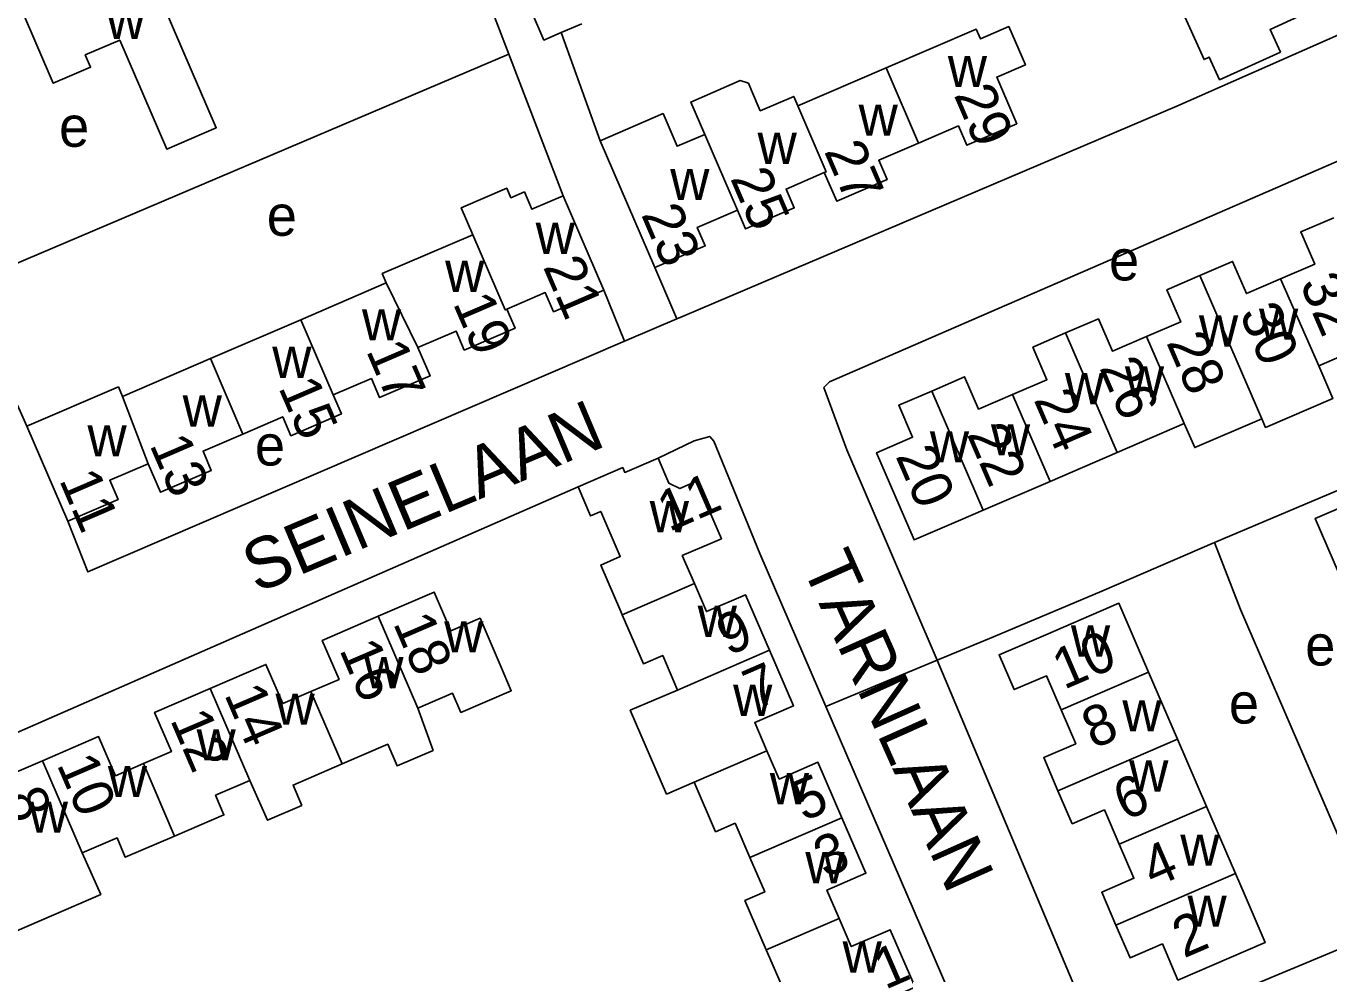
# Model space of a CAD drawing. Extents: x 157768 to 159790, y 387230 to 389604.
# Drawn here: x 158163.8 to 158292.2, y 388618.6 to 388712 of the extents above; entities that cross this region are included whole.
import ezdxf

# ---------------------------------------------------------------- set-up
doc = ezdxf.new("R2010")
doc.units = 0
for name, color, linetype in [('BLT_Basislijn', 7, 'Continuous'), ('BLT_Bebouwing', 7, 'Continuous'), ('BLT_Centroide', 7, 'Continuous'), ('BLT_Huisnummer', 7, 'Continuous'), ('BLT_Huisnummer_ tussenligend', 7, 'Continuous'), ('BLT_Onderverdeling_panden', 7, 'Continuous'), ('BLT_Straatnaam', 7, 'Continuous'), ('BLT_Vlakafsluiter', 7, 'Continuous')]:
    doc.layers.add(name, color=color, linetype=linetype)

msp = doc.modelspace()

# ---------------------------------------------------------------- linework, layer by layer
at = {"layer": 'BLT_Basislijn'}
for p, q in [((158211.37, 388709.21), (158205.74, 388723.88)), ((158220.36, 388700.68), (158216.53, 388711.33)), ((158157.67, 388686.38), (158211.37, 388709.21)), ((158216.72, 388695.26), (158211.37, 388709.21)), ((158227.91, 388683.12), (158225.75, 388688.17)), ((158163.87, 388672.54), (158157.67, 388686.38)), ((158222.77, 388680.91), (158220.72, 388685.96))]:
    msp.add_line(p, q, dxfattribs=at)
for points in [[(158228.87, 388771.67), (158290.41, 388727.23), (158290.89, 388726.75), (158296.54, 388713.1), (158296.49, 388712.58), (158277.19, 388704.08), (158228.72, 388683.47), (158227.91, 388683.12)], [(158253.57, 388649.48), (158244.69, 388670.2), (158242.42, 388676.37), (158242.96, 388676.91), (158323.61, 388711.93)], [(158222.77, 388680.91), (158223.24, 388681.11), (158227.91, 388683.12)], [(158167.9, 388663.18), (158169.88, 388658.18), (158222.77, 388680.91)], [(158226.07, 388669.41), (158229.62, 388671.09), (158231.17, 388671.54), (158231.58, 388671.07), (158236.09, 388660.01), (158242.61, 388644.93)], [(158303.84, 388670.77), (158292.19, 388665.85), (158280.9, 388661.07)], [(158121.28, 388623.33), (158122.08, 388624.5), (158218.19, 388666.56)], [(158280.9, 388661.07), (158269.8, 388656.28), (158259.12, 388651.77), (158253.57, 388649.48)], [(158280.9, 388661.07), (158283.46, 388654.49), (158297.22, 388622.68)], [(158253.57, 388649.48), (158269.51, 388611.63), (158271, 388611.74), (158297.22, 388622.68)], [(158242.61, 388644.93), (158255.37, 388615.4), (158255.28, 388614.44), (158187.04, 388585.65), (158156.23, 388567.27)]]:
    msp.add_lwpolyline(points, dxfattribs=at)
at = {"layer": 'BLT_Bebouwing'}
for p, q in [((158218.55, 388712.2), (158216.53, 388711.33)), ((158239.84, 388704.11), (158248.55, 388707.86)), ((158225.75, 388688.17), (158220.36, 388700.68)), ((158216.72, 388695.26), (158220.72, 388685.96)), ((158190.86, 388683.04), (158199.28, 388686.67)), ((158181.95, 388679.21), (158190.86, 388683.04)), ((158173.29, 388675.48), (158181.95, 388679.21)), ((158167.9, 388663.18), (158163.87, 388672.54)), ((158271.32, 388669.95), (158277.92, 388672.8)), ((158264.71, 388667.1), (158271.32, 388669.95)), ((158258.1, 388664.26), (158264.71, 388667.1)), ((158277.26, 388641.7), (158274.41, 388648.31)), ((158280.12, 388635.07), (158277.26, 388641.7)), ((158282.97, 388628.46), (158280.12, 388635.07))]:
    msp.add_line(p, q, dxfattribs=at)
for points in [[(158169.97, 388720.68), (158170.31, 388719.87), (158174.1, 388721.5), (158182.53, 388701.95), (158177.66, 388699.85), (158173.02, 388710.59), (158169.62, 388709.13), (158170.14, 388707.93), (158166.46, 388706.35), (158161.81, 388717.15), (158169.97, 388720.68)], [(158282.98, 388721.85), (158285.21, 388716.94), (158286.99, 388717.74), (158289.18, 388712.92), (158286.39, 388711.65), (158287.41, 388709.42), (158281.42, 388706.68), (158280.4, 388708.92), (158279.89, 388708.68), (158275.94, 388717.43)], [(158216.53, 388711.33), (158214.82, 388710.6), (158213.6, 388713.41), (158215.41, 388714.19)], [(158248.55, 388707.86), (158257.42, 388711.68), (158257.84, 388710.71), (158260.65, 388711.93), (158262.28, 388708.16), (158259.46, 388706.95), (158261.43, 388702.35), (158256.5, 388700.23), (158255.68, 388702.13), (158251.75, 388700.44)], [(158230.67, 388701.3), (158229.29, 388704.49), (158234.18, 388706.6), (158234.98, 388706.36), (158235.29, 388705.64), (158236.15, 388703.63), (158239.44, 388705.05), (158239.84, 388704.11)], [(158220.36, 388700.68), (158226.56, 388703.35), (158227.94, 388700.13), (158230.67, 388701.3)], [(158251.75, 388700.44), (158247.83, 388698.75), (158248.64, 388696.85), (158243.68, 388694.71), (158242.46, 388697.54)], [(158242.46, 388697.54), (158238.69, 388695.91), (158239.49, 388694.06), (158234.7, 388691.99), (158233.9, 388693.84)], [(158207.81, 388691.42), (158206.67, 388694.07), (158211.16, 388696.01), (158211.57, 388695.06), (158212.9, 388695.63), (158213.64, 388693.93), (158216.72, 388695.26)], [(158233.9, 388693.84), (158229.94, 388692.14), (158230.73, 388690.31), (158225.75, 388688.17)], [(158287.42, 388687.07), (158290.79, 388688.51), (158289.42, 388691.69), (158292.66, 388693.09)], [(158199.28, 388686.67), (158198.89, 388687.58), (158207.81, 388691.42)], [(158279.46, 388687.4), (158282.69, 388688.79), (158284.06, 388685.62), (158287.42, 388687.07)], [(158274.22, 388681.38), (158277.59, 388682.83), (158276.23, 388686), (158279.46, 388687.4)], [(158220.72, 388685.96), (158215.77, 388683.83), (158214.95, 388685.71), (158211.18, 388684.08)], [(158211.18, 388684.08), (158211.99, 388682.2), (158206.98, 388680.04), (158206.17, 388681.92), (158202.4, 388680.3)], [(158266.24, 388681.73), (158269.48, 388683.12), (158270.86, 388679.93), (158274.22, 388681.38)], [(158261.02, 388675.68), (158264.39, 388677.13), (158263.01, 388680.33), (158266.24, 388681.73)], [(158291.18, 388678.51), (158297.78, 388681.36)], [(158202.4, 388680.3), (158203.61, 388677.5), (158198.63, 388675.36), (158197.82, 388677.24), (158194.06, 388675.62)], [(158253.04, 388676.01), (158256.28, 388677.41), (158257.65, 388674.23), (158261.02, 388675.68)], [(158285.58, 388673.28), (158285.95, 388672.42), (158292.56, 388675.27), (158291.18, 388678.51)], [(158163.87, 388672.54), (158172.89, 388676.42), (158173.29, 388675.48)], [(158258.1, 388664.26), (158255.9, 388663.31), (158251.31, 388661.33), (158247.61, 388669.93), (158251.15, 388671.46), (158249.79, 388674.61), (158253.04, 388676.01)], [(158194.06, 388675.62), (158194.86, 388673.75), (158189.89, 388671.61), (158189.09, 388673.47), (158185.16, 388671.77)], [(158277.92, 388672.8), (158278.97, 388670.43), (158285.58, 388673.28)], [(158185.16, 388671.77), (158181.23, 388670.08), (158182.04, 388668.19), (158177.04, 388666.04), (158175.83, 388668.85)], [(158175.83, 388668.85), (158172.04, 388667.21), (158172.86, 388665.31), (158167.9, 388663.18)], [(158226.07, 388669.41), (158222.79, 388667.99), (158222.59, 388668.46), (158218.19, 388666.56)], [(158229.65, 388657.04), (158228.46, 388659.8), (158232.31, 388661.46), (158229.87, 388667.12), (158228.22, 388666.4), (158227.14, 388666.93), (158226.07, 388669.41)], [(158293.77, 388656.69), (158290.85, 388663.46), (158298.03, 388666.55), (158302.62, 388668.53), (158304.09, 388665.14), (158300.93, 388663.78), (158302.38, 388660.4)], [(158218.19, 388666.56), (158219.42, 388663.71), (158220.42, 388664.14), (158222.34, 388659.69), (158220.42, 388658.86), (158222.4, 388654.27), (158222.54, 388653.96)], [(158237.05, 388650.46), (158234.68, 388655.94), (158230.84, 388654.28), (158229.65, 388657.04)], [(158202.39, 388644.76), (158205.82, 388646.23), (158206.64, 388644.33), (158211.6, 388646.47), (158210.51, 388649.02), (158208.53, 388653.61), (158205.65, 388652.37), (158204.01, 388656.19), (158198.49, 388653.82)], [(158274.41, 388648.31), (158271.49, 388655.09), (158264.29, 388651.98), (158259.69, 388650), (158261.17, 388646.58), (158264.35, 388647.95), (158265.8, 388644.6)], [(158198.49, 388653.82), (158192.98, 388651.44), (158194.64, 388647.59), (158191.86, 388646.39)], [(158222.54, 388653.96), (158224.63, 388649.13), (158226.53, 388649.95), (158228, 388646.54)], [(158236.8, 388640.55), (158235.6, 388643.33), (158239.42, 388644.98), (158237.05, 388650.46)], [(158191.86, 388646.39), (158189.08, 388645.2), (158187.42, 388649.06), (158181.93, 388646.7)], [(158181.93, 388646.7), (158176.45, 388644.34), (158178.11, 388640.47), (158175.36, 388639.29)], [(158228, 388646.54), (158223.34, 388644.55), (158226.91, 388636.29), (158229.64, 388637.45)], [(158194.93, 388639.27), (158199.43, 388641.2), (158200.35, 388639.07), (158203.9, 388640.6), (158202.39, 388644.76)], [(158265.8, 388644.6), (158267.24, 388641.25), (158264.08, 388639.89), (158265.48, 388636.62)], [(158175.36, 388639.29), (158172.6, 388638.1), (158170.94, 388641.96), (158165.4, 388639.58)], [(158244.2, 388633.95), (158241.83, 388639.42), (158238.01, 388637.77), (158236.8, 388640.55)], [(158165.4, 388639.58), (158159.86, 388637.19), (158161.54, 388633.3), (158158.8, 388632.12)], [(158185.84, 388637.63), (158187.57, 388633.71), (158190.96, 388635.17), (158190.1, 388637.18), (158194.93, 388639.27)], [(158178.43, 388632.15), (158183.29, 388634.24), (158182.46, 388636.17), (158185.84, 388637.63)], [(158229.64, 388637.45), (158231.74, 388632.58), (158233.66, 388633.41), (158235.12, 388630.03)], [(158265.48, 388636.62), (158266.89, 388633.36), (158270.07, 388634.73), (158271.52, 388631.36)], [(158243.92, 388624.04), (158242.71, 388626.82), (158246.56, 388628.49), (158244.2, 388633.95)], [(158169.32, 388630.49), (158172.75, 388631.97), (158173.57, 388630.06), (158178.43, 388632.15)], [(158271.52, 388631.36), (158272.97, 388627.99), (158269.8, 388626.62), (158271.19, 388623.38)], [(158161.86, 388625.01), (158162.89, 388622.82), (158171.14, 388626.4), (158169.32, 388630.49)], [(158235.12, 388630.03), (158236.58, 388626.65), (158234.63, 388625.8), (158236.74, 388620.94)], [(158271.19, 388623.38), (158272.59, 388620.15), (158275.78, 388621.52), (158277.31, 388617.96), (158285.9, 388621.66), (158283.92, 388626.25), (158282.97, 388628.46)], [(158236.74, 388620.94), (158236.87, 388620.65), (158238.85, 388616.06), (158240.77, 388616.89), (158242.32, 388613.32), (158251.41, 388617.26), (158248.96, 388622.92), (158245.12, 388621.26), (158243.92, 388624.04)]]:
    msp.add_lwpolyline(points, dxfattribs=at)
at = {"layer": 'BLT_Onderverdeling_panden'}
for p, q in [((158251.75, 388700.44), (158248.55, 388707.86)), ((158233.9, 388693.84), (158230.67, 388701.3)), ((158202.4, 388680.3), (158199.28, 388686.67)), ((158279.46, 388687.4), (158285.58, 388673.28)), ((158287.42, 388687.07), (158291.18, 388678.51)), ((158194.06, 388675.62), (158190.86, 388683.04)), ((158266.24, 388681.73), (158271.32, 388669.95)), ((158274.22, 388681.38), (158277.92, 388672.8)), ((158185.16, 388671.77), (158181.95, 388679.21)), ((158253.04, 388676.01), (158258.1, 388664.26)), ((158173.29, 388675.48), (158175.83, 388668.85)), ((158261.02, 388675.68), (158264.71, 388667.1)), ((158229.65, 388657.04), (158222.54, 388653.96)), ((158198.49, 388653.82), (158202.39, 388644.76)), ((158237.05, 388650.46), (158228, 388646.54)), ((158265.8, 388644.6), (158274.41, 388648.31)), ((158181.93, 388646.7), (158185.84, 388637.63)), ((158191.86, 388646.39), (158194.93, 388639.27)), ((158265.48, 388636.62), (158277.26, 388641.7)), ((158236.8, 388640.55), (158229.64, 388637.45)), ((158165.4, 388639.58), (158169.32, 388630.49)), ((158175.36, 388639.29), (158178.43, 388632.15)), ((158271.52, 388631.36), (158280.12, 388635.07)), ((158244.2, 388633.95), (158235.12, 388630.03)), ((158271.19, 388623.38), (158282.97, 388628.46)), ((158243.92, 388624.04), (158236.74, 388620.94))]:
    msp.add_line(p, q, dxfattribs=at)
for points in [[(158239.84, 388704.11), (158242.63, 388697.61), (158242.46, 388697.54)], [(158211.18, 388684.08), (158211.01, 388684.01), (158207.81, 388691.42)]]:
    msp.add_lwpolyline(points, dxfattribs=at)
at = {"layer": 'BLT_Vlakafsluiter'}
msp.add_line((158242.61, 388644.93), (158253.57, 388649.48), dxfattribs=at)

# ---------------------------------------------------------------- texts
at = {"layer": 'BLT_Centroide'}
for s, p in [('w', (158171.68, 388710.69)), ('w', (158254.63, 388705.97)), ('w', (158245.84, 388701.17)), ('e', (158167.04, 388700.08)), ('w', (158235.88, 388698.39)), ('w', (158227.27, 388694.83)), ('e', (158187.51, 388691.31)), ('w', (158214.01, 388689.53)), ('w', (158205.09, 388685.78)), ('e', (158270.52, 388686.91)), ('w', (158196.89, 388681)), ('w', (158285.3, 388681.06)), ('w', (158279.38, 388680.39)), ('w', (158188.05, 388677.31)), ('w', (158266.17, 388674.7)), ('w', (158272.08, 388675.38)), ('w', (158179.22, 388672.5)), ('w', (158169.84, 388669.56)), ('w', (158258.88, 388669.67)), ('e', (158186.34, 388668.67)), ('w', (158252.86, 388668.97)), ('w', (158225.25, 388662.09)), ('w', (158229.98, 388651.78)), ('w', (158205, 388650.25)), ('w', (158266.76, 388649.84)), ('e', (158289.85, 388648.96)), ('w', (158197.12, 388646.72)), ('w', (158233.47, 388644)), ('w', (158188.37, 388643.12)), ('w', (158271.83, 388642.47)), ('e', (158282.33, 388643.24)), ('w', (158180.59, 388639.61)), ('w', (158171.85, 388636)), ('w', (158272.5, 388636.53)), ('w', (158237.09, 388635.28)), ('w', (158164.06, 388632.48)), ('w', (158277.54, 388629.22)), ('w', (158240.59, 388627.5)), ('w', (158278.25, 388623.22)), ('w', (158244.26, 388618.69))]:
    msp.add_text(s, height=4, dxfattribs=at).set_placement(p)
at = {"layer": 'BLT_Huisnummer'}
for s, rotation, p in [('29', 293.2975, (158255.19, 388705.21)), ('23', 293.2975, (158224.37, 388693.42)), ('21', 293.2975, (158214.7, 388688.27)), ('32', 293.3095, (158289.28, 388686.6)), ('28', 293.3095, (158276.13, 388680.81)), ('15', 293.2975, (158188.62, 388676.37)), ('24', 293.3095, (158263.06, 388675.18)), ('20', 293.3095, (158249.44, 388669.62)), ('11', 293.2975, (158167.01, 388667.26)), ('11', 23.3967, (158227.15, 388662.1)), ('18', 293.2983, (158199.92, 388653.14)), ('10', 23.3121, (158266.07, 388646.55)), ('14', 293.2983, (158183.28, 388646.13)), ('10', 293.2983, (158166.77, 388639.23)), ('5', 23.3967, (158240.42, 388633.56)), ('6', 23.3121, (158272.08, 388633.62)), ('2', 23.3121, (158277.89, 388620.08)), ('1', 23.3967, (158248.45, 388616.98))]:
    msp.add_text(s, height=4, rotation=rotation, dxfattribs=at).set_placement(p)
at = {"layer": 'BLT_Huisnummer_ tussenligend'}
for s, rotation, p in [('27', 293.2975, (158242.4, 388699.66)), ('25', 293.2975, (158233.15, 388696.99)), ('19', 293.2975, (158205.82, 388684.67)), ('30', 293.3095, (158283.33, 388683.66)), ('17', 293.2975, (158197.26, 388680)), ('26', 293.3095, (158269.53, 388678.33)), ('22', 293.3095, (158256.47, 388671.78)), ('13', 293.2975, (158175.92, 388670.72)), ('9', 23.3967, (158232.98, 388649.88)), ('16', 293.2983, (158194.62, 388650.53)), ('7', 23.3967, (158235.61, 388644.55)), ('8', 23.3121, (158268.98, 388640.7)), ('12', 293.2983, (158177.95, 388643.62)), ('8', 293.2983, (158161.61, 388635.93)), ('3', 23.3967, (158242.54, 388627.97)), ('4', 23.3121, (158274.87, 388627.01))]:
    msp.add_text(s, height=4, rotation=rotation, dxfattribs=at).set_placement(p)
at = {"layer": 'BLT_Straatnaam'}
for s, rotation, p in [('SEINELAAN', 22.9195, (158186.52, 388656.04)), ('TARNLAAN', 294.0828, (158240.19, 388658.84))]:
    msp.add_text(s, height=5, rotation=rotation, dxfattribs=at).set_placement(p)

doc.saveas('drawing.dxf')
